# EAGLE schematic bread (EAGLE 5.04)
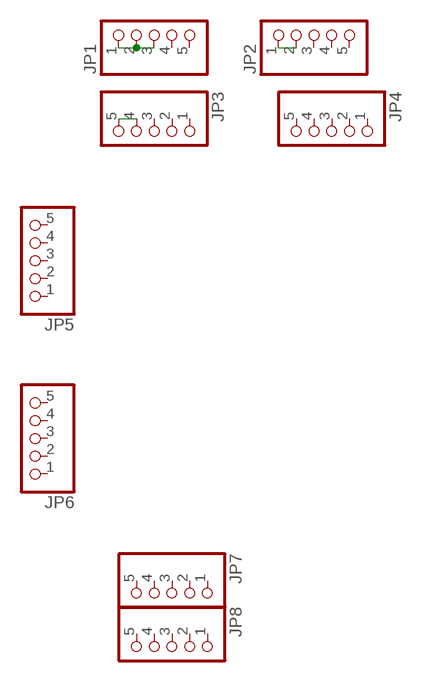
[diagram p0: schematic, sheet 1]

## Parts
JP1  PINHD-1X5  [1X05]
JP2  PINHD-1X5  [1X05]
JP3  PINHD-1X5  [1X05]
JP4  PINHD-1X5  [1X05]
JP5  PINHD-1X5  [1X05]
JP6  PINHD-1X5  [1X05]
JP7  PINHD-1X5  [1X05]
JP8  PINHD-1X5  [1X05]

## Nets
N$1: JP1.1 JP1.2 JP1.3
N$2: JP2.1 JP2.2
N$3: JP3.4 JP3.5
Unconnected: JP1.4 JP1.5 JP2.3 JP2.4 JP2.5 JP3.1 JP3.2 JP3.3 JP4.1 JP4.2 JP4.3 JP4.4 JP4.5 JP5.1 JP5.2 JP5.3 JP5.4 JP5.5 JP6.1 JP6.2 JP6.3 JP6.4 JP6.5 JP7.1 JP7.2 JP7.3 JP7.4 JP7.5 JP8.1 JP8.2 JP8.3 JP8.4 JP8.5

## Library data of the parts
JP1-JP8 = pinhead(2):PINHD-1X5: PIN HEADER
